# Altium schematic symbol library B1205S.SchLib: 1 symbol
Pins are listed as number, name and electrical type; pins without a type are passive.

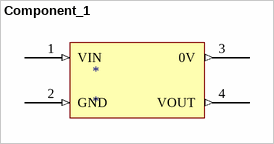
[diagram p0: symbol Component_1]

## Component_1
designator *
footprint Model Name (Footprint not found)
pins: 1 VIN (in), 2 GND (in), 3 0V (out), 4 VOUT (out)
